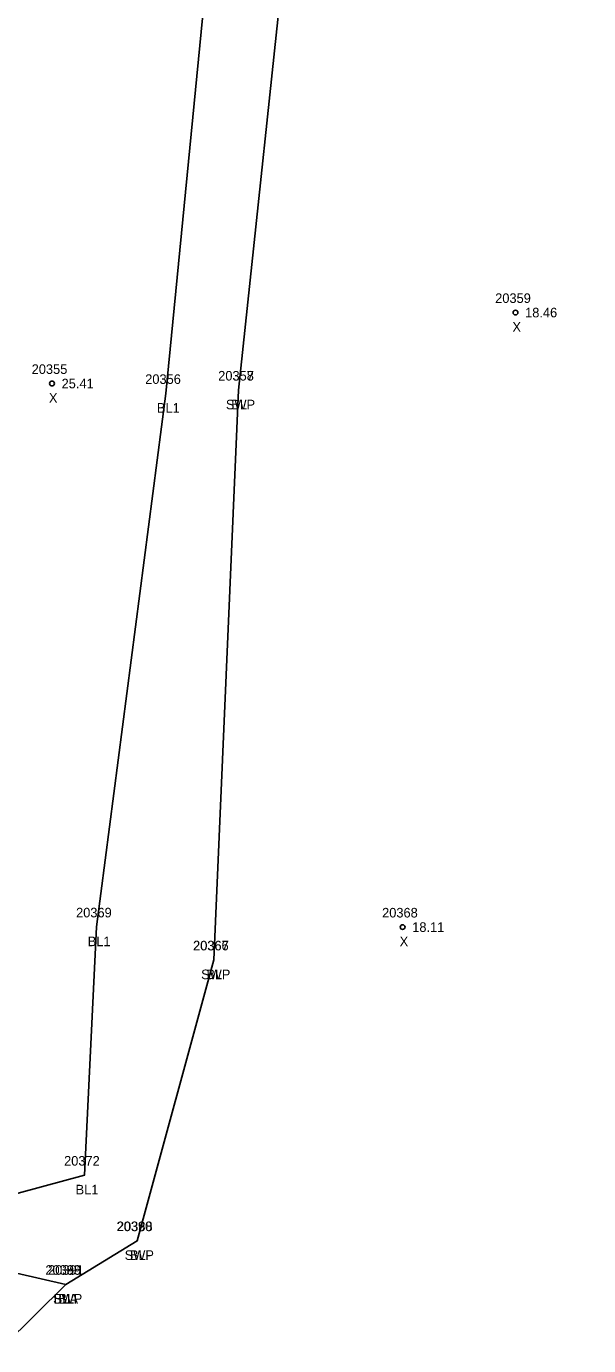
# Model space of a CAD drawing. Extents: x 2432729 to 2433340, y 684958 to 688103.
# Drawn here: x 2433168.9 to 2433227.5, y 686062.5 to 686200.1 of the extents above; entities that cross this region are included whole.
import ezdxf

# ---------------------------------------------------------------- set-up
doc = ezdxf.new("R2010")
doc.units = 0
for name, color, linetype in [('RD_DTM_BkLn1', 7, 'Continuous'), ('RD_EX_H2O', 7, 'Continuous'), ('RD_EX_H2O_txCode', 7, 'Continuous'), ('RD_Sketch8', 7, 'Continuous'), ('RD_SMD_Locator', 7, 'Continuous'), ('RD_SMD_Misc', 7, 'Continuous')]:
    doc.layers.add(name, color=color, linetype=linetype)

msp = doc.modelspace()

# ---------------------------------------------------------------- linework, layer by layer
at = {"layer": 'RD_DTM_BkLn1'}
for points in [[(2433121.01, 686546.89), (2433138.81, 686483.59), (2433156.33, 686436.44), (2433172.33, 686382.63), (2433186.16, 686325.49), (2433196.85, 686279.41), (2433196.3, 686212.3), (2433190.98, 686162.16), (2433188.39, 686102.75), (2433180.42, 686073.48), (2433172.96, 686068.93), (2433166.53, 686062.55), (2433152.82, 686065.09)], [(2433099.45, 686534.09), (2433116.42, 686534.99), (2433132.92, 686481.52), (2433149.46, 686435.57), (2433165.09, 686381.24), (2433180.28, 686324.44), (2433185.06, 686269.22), (2433188.28, 686211.65), (2433183.39, 686161.81), (2433176.18, 686106.19), (2433174.91, 686080.31), (2433163.5, 686077.21), (2433155.14, 686078.25)], [(2433172.96, 686068.93), (2433154.49, 686073.14), (2433144.74, 686075.18), (2433129.23, 686077.37), (2433110.48, 686084.68)]]:
    msp.add_lwpolyline(points, dxfattribs=at)
at = {"layer": 'RD_EX_H2O'}
msp.add_lwpolyline([(2433227.48, 686289.61), (2433196.85, 686279.41), (2433196.3, 686212.3), (2433190.98, 686162.16), (2433188.39, 686102.75), (2433180.42, 686073.48), (2433172.96, 686068.93), (2433166.53, 686062.55)], dxfattribs=at)
at = {"layer": 'RD_SMD_Locator'}
for centre, radius in [((2433219.86, 686170.25), 0.25), ((2433171.53, 686162.85), 0.25), ((2433183.39, 686161.81), 0.001), ((2433190.98, 686162.16), 0.001), ((2433190.98, 686162.16), 0.001), ((2433176.18, 686106.19), 0.001), ((2433208.09, 686106.18), 0.25), ((2433188.39, 686102.75), 0.001), ((2433188.39, 686102.75), 0.001), ((2433174.91, 686080.31), 0.001), ((2433180.42, 686073.48), 0.001), ((2433180.42, 686073.48), 0.001), ((2433172.96, 686068.93), 0.001), ((2433172.96, 686068.93), 0.001), ((2433172.96, 686068.93), 0.001)]:
    msp.add_circle(centre, radius, dxfattribs=at)

# ---------------------------------------------------------------- texts
at = {"layer": 'RD_EX_H2O_txCode'}
for s, p in [('20357', (2433188.86, 686163.16)), ('SWP', (2433189.66, 686160.16)), ('20366', (2433186.23, 686103.75)), ('SWP', (2433187.08, 686100.75)), ('20388', (2433178.3, 686074.48)), ('SWP', (2433179.11, 686071.48)), ('20389', (2433170.84, 686069.93)), ('SWP', (2433171.64, 686066.93))]:
    msp.add_text(s, height=1, dxfattribs=at).set_placement(p)
at = {"layer": 'RD_Sketch8'}
for s, p in [('20359', (2433217.74, 686171.25)), ('18.46', (2433220.86, 686169.75)), ('X', (2433219.54, 686168.25)), ('20355', (2433169.41, 686163.85)), ('25.41', (2433172.53, 686162.35)), ('X', (2433171.21, 686160.85)), ('20368', (2433205.95, 686107.18)), ('18.11', (2433209.09, 686105.68)), ('X', (2433207.78, 686104.18))]:
    msp.add_text(s, height=1, dxfattribs=at).set_placement(p)
at = {"layer": 'RD_SMD_Misc'}
for s, p in [('20358', (2433188.86, 686163.16)), ('20356', (2433181.25, 686162.81)), ('BL', (2433190.22, 686160.16)), ('BL1', (2433182.47, 686159.81)), ('20369', (2433174.04, 686107.19)), ('BL1', (2433175.26, 686104.19)), ('20367', (2433186.25, 686103.75)), ('BL', (2433187.64, 686100.75)), ('20372', (2433172.79, 686081.31)), ('BL1', (2433173.99, 686078.31)), ('20390', (2433178.26, 686074.48)), ('BL', (2433179.66, 686071.48)), ('20395', (2433170.84, 686069.93)), ('20391', (2433171.12, 686069.93)), ('BLA', (2433171.71, 686066.93)), ('BL', (2433172.2, 686066.93))]:
    msp.add_text(s, height=1, dxfattribs=at).set_placement(p)

doc.saveas('drawing.dxf')
